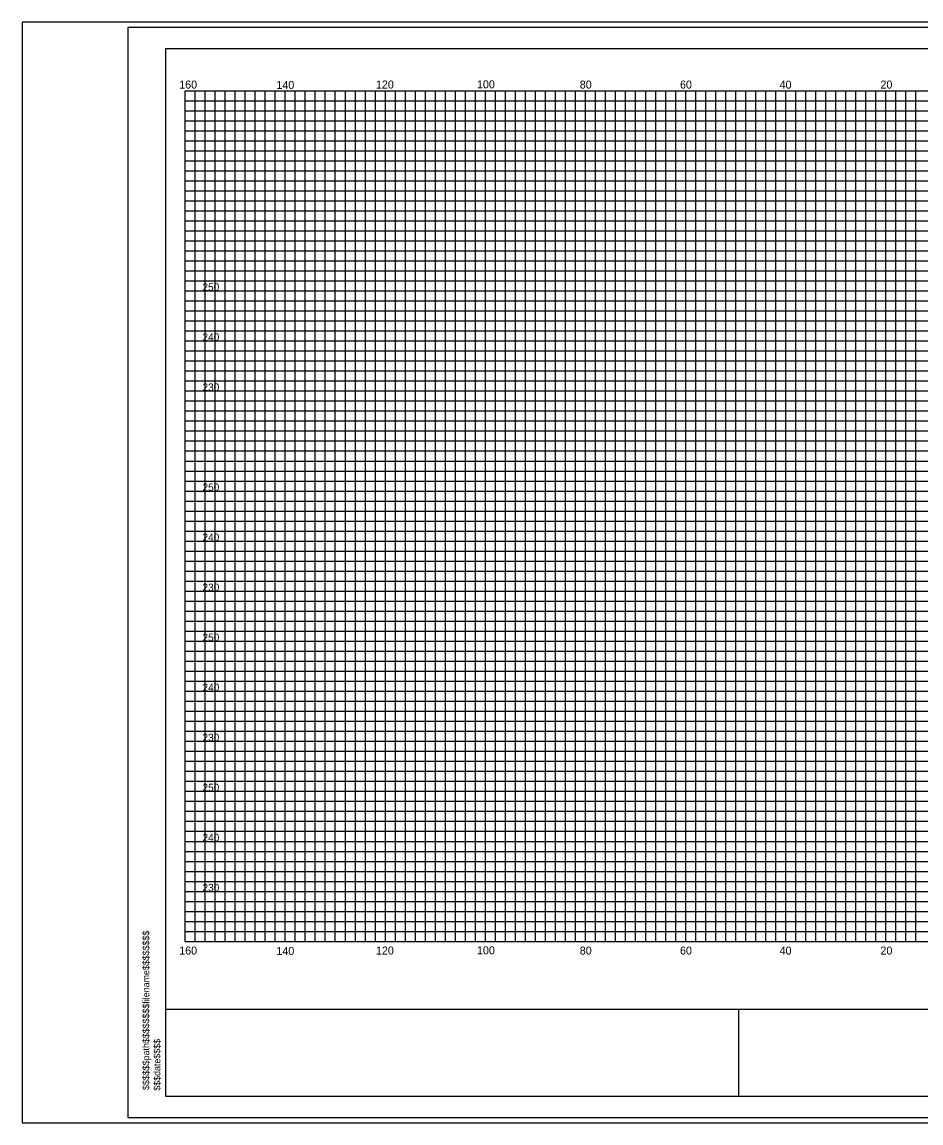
# Model space of a CAD drawing. Extents: x 967 to 1326, y 964 to 1744.
# Drawn here: x 967.4 to 1147, y 963.7 to 1183.7 of the extents above; entities that cross this region are included whole.
import ezdxf

# ---------------------------------------------------------------- set-up
doc = ezdxf.new("R2010")
doc.units = 0
for name, color, linetype in [('Default', 7, 'Continuous'), ('RD_PD_PaveShd', 7, 'Continuous'), ('RD_XS_CurbBase', 7, 'Continuous'), ('RD_XS_TX_Elev_PR', 7, 'Continuous'), ('RD_XS_TX_MkPT', 7, 'Continuous'), ('RD_XS_TX_Slope', 7, 'Continuous'), ('RD_XS_TX_TOC', 7, 'Continuous')]:
    doc.layers.add(name, color=color, linetype=linetype)

msp = doc.modelspace()

# ---------------------------------------------------------------- linework, layer by layer
at = {"layer": 'RD_PD_PaveShd'}
for p, q in [((996.11, 968.98), (996.11, 1178.46)), ((996.11, 1178.46), (1323.89, 1178.46)), ((996.11, 986.49), (1323.89, 986.49)), ((1110.59, 968.98), (1110.59, 986.56)), ((1323.89, 968.98), (996.11, 968.98))]:
    msp.add_line(p, q, dxfattribs=at)
at = {"layer": 'RD_XS_CurbBase'}
msp.add_lwpolyline([(967.41, 963.72), (1326.28, 963.72), (1326.28, 1183.72), (967.41, 1183.72)], close=True, dxfattribs=at)
at = {"layer": 'RD_XS_TX_Elev_PR'}
for p, q in [((1000, 1170), (1320, 1170)), ((1000, 1000), (1000, 1170)), ((1010, 1000), (1010, 1170)), ((1020, 1000), (1020, 1170)), ((1030, 1000), (1030, 1170)), ((1040, 1000), (1040, 1170)), ((1050, 1000), (1050, 1170)), ((1060, 1000), (1060, 1170)), ((1070, 1000), (1070, 1170)), ((1080, 1000), (1080, 1170)), ((1090, 1000), (1090, 1170)), ((1100, 1000), (1100, 1170)), ((1110, 1000), (1110, 1170)), ((1120, 1000), (1120, 1170)), ((1130, 1000), (1130, 1170)), ((1140, 1000), (1140, 1170)), ((1000, 1160), (1320, 1160)), ((1000, 1150), (1320, 1150)), ((1000, 1140), (1320, 1140)), ((1000, 1130), (1320, 1130)), ((1000, 1120), (1320, 1120)), ((1000, 1110), (1320, 1110)), ((1000, 1100), (1320, 1100)), ((1000, 1090), (1320, 1090)), ((1000, 1080), (1320, 1080)), ((1000, 1070), (1320, 1070)), ((1000, 1060), (1320, 1060)), ((1000, 1050), (1320, 1050)), ((1000, 1040), (1320, 1040)), ((1000, 1030), (1320, 1030)), ((1000, 1020), (1320, 1020)), ((1000, 1010), (1320, 1010)), ((1000, 1000), (1320, 1000))]:
    msp.add_line(p, q, dxfattribs=at)
at = {"layer": 'RD_XS_TX_Slope'}
for p, q in [((1002, 1000), (1002, 1170)), ((1004, 1000), (1004, 1170)), ((1006, 1000), (1006, 1170)), ((1008, 1000), (1008, 1170)), ((1012, 1000), (1012, 1170)), ((1014, 1000), (1014, 1170)), ((1016, 1000), (1016, 1170)), ((1018, 1000), (1018, 1170)), ((1022, 1000), (1022, 1170)), ((1024, 1000), (1024, 1170)), ((1026, 1000), (1026, 1170)), ((1028, 1000), (1028, 1170)), ((1032, 1000), (1032, 1170)), ((1034, 1000), (1034, 1170)), ((1036, 1000), (1036, 1170)), ((1038, 1000), (1038, 1170)), ((1042, 1000), (1042, 1170)), ((1044, 1000), (1044, 1170)), ((1046, 1000), (1046, 1170)), ((1048, 1000), (1048, 1170)), ((1052, 1000), (1052, 1170)), ((1054, 1000), (1054, 1170)), ((1056, 1000), (1056, 1170)), ((1058, 1000), (1058, 1170)), ((1062, 1000), (1062, 1170)), ((1064, 1000), (1064, 1170)), ((1066, 1000), (1066, 1170)), ((1068, 1000), (1068, 1170)), ((1072, 1000), (1072, 1170)), ((1074, 1000), (1074, 1170)), ((1076, 1000), (1076, 1170)), ((1078, 1000), (1078, 1170)), ((1082, 1000), (1082, 1170)), ((1084, 1000), (1084, 1170)), ((1086, 1000), (1086, 1170)), ((1088, 1000), (1088, 1170)), ((1092, 1000), (1092, 1170)), ((1094, 1000), (1094, 1170)), ((1096, 1000), (1096, 1170)), ((1098, 1000), (1098, 1170)), ((1102, 1000), (1102, 1170)), ((1104, 1000), (1104, 1170)), ((1106, 1000), (1106, 1170)), ((1108, 1000), (1108, 1170)), ((1112, 1000), (1112, 1170)), ((1114, 1000), (1114, 1170)), ((1116, 1000), (1116, 1170)), ((1118, 1000), (1118, 1170)), ((1122, 1000), (1122, 1170)), ((1124, 1000), (1124, 1170)), ((1126, 1000), (1126, 1170)), ((1128, 1000), (1128, 1170)), ((1132, 1000), (1132, 1170)), ((1134, 1000), (1134, 1170)), ((1136, 1000), (1136, 1170)), ((1138, 1000), (1138, 1170)), ((1142, 1000), (1142, 1170)), ((1144, 1000), (1144, 1170)), ((1146, 1000), (1146, 1170)), ((1000, 1168), (1320, 1168)), ((1000, 1166), (1320, 1166)), ((1000, 1164), (1320, 1164)), ((1000, 1162), (1320, 1162)), ((1000, 1158), (1320, 1158)), ((1000, 1156), (1320, 1156)), ((1000, 1154), (1320, 1154)), ((1000, 1152), (1320, 1152)), ((1000, 1148), (1320, 1148)), ((1000, 1146), (1320, 1146)), ((1000, 1144), (1320, 1144)), ((1000, 1142), (1320, 1142)), ((1000, 1138), (1320, 1138)), ((1000, 1136), (1320, 1136)), ((1000, 1134), (1320, 1134)), ((1000, 1132), (1320, 1132)), ((1000, 1128), (1320, 1128)), ((1000, 1126), (1320, 1126)), ((1000, 1124), (1320, 1124)), ((1000, 1122), (1320, 1122)), ((1000, 1118), (1320, 1118)), ((1000, 1116), (1320, 1116)), ((1000, 1114), (1320, 1114)), ((1000, 1112), (1320, 1112)), ((1000, 1108), (1320, 1108)), ((1000, 1106), (1320, 1106)), ((1000, 1104), (1320, 1104)), ((1000, 1102), (1320, 1102)), ((1000, 1098), (1320, 1098)), ((1000, 1096), (1320, 1096)), ((1000, 1094), (1320, 1094)), ((1000, 1092), (1320, 1092)), ((1000, 1088), (1320, 1088)), ((1000, 1086), (1320, 1086)), ((1000, 1084), (1320, 1084)), ((1000, 1082), (1320, 1082)), ((1000, 1078), (1320, 1078)), ((1000, 1076), (1320, 1076)), ((1000, 1074), (1320, 1074)), ((1000, 1072), (1320, 1072)), ((1000, 1068), (1320, 1068)), ((1000, 1066), (1320, 1066)), ((1000, 1064), (1320, 1064)), ((1000, 1062), (1320, 1062)), ((1000, 1058), (1320, 1058)), ((1000, 1056), (1320, 1056)), ((1000, 1054), (1320, 1054)), ((1000, 1052), (1320, 1052)), ((1000, 1048), (1320, 1048)), ((1000, 1046), (1320, 1046)), ((1000, 1044), (1320, 1044)), ((1000, 1042), (1320, 1042)), ((1000, 1038), (1320, 1038)), ((1000, 1036), (1320, 1036)), ((1000, 1034), (1320, 1034)), ((1000, 1032), (1320, 1032)), ((1000, 1028), (1320, 1028)), ((1000, 1026), (1320, 1026)), ((1000, 1024), (1320, 1024)), ((1000, 1022), (1320, 1022)), ((1000, 1018), (1320, 1018)), ((1000, 1016), (1320, 1016)), ((1000, 1014), (1320, 1014)), ((1000, 1012), (1320, 1012)), ((1000, 1008), (1320, 1008)), ((1000, 1006), (1320, 1006)), ((1000, 1004), (1320, 1004)), ((1000, 1002), (1320, 1002))]:
    msp.add_line(p, q, dxfattribs=at)
at = {"layer": 'RD_XS_TX_TOC'}
for points in [[(967.41, 963.72), (1326.28, 963.72), (1326.28, 1183.72), (967.41, 1183.72)], [(988.52, 964.84), (1326.28, 964.84), (1326.28, 1182.6), (988.52, 1182.6)]]:
    msp.add_lwpolyline(points, close=True, dxfattribs=at)

# ---------------------------------------------------------------- texts
at = {"layer": 'Default'}
for s, p in [('250', (1003.47, 1130)), ('240', (1003.47, 1120)), ('230', (1003.47, 1110)), ('250', (1003.47, 1090)), ('240', (1003.47, 1080)), ('230', (1003.47, 1070)), ('250', (1003.47, 1060)), ('240', (1003.47, 1050)), ('230', (1003.47, 1040)), ('250', (1003.47, 1030)), ('240', (1003.47, 1020)), ('230', (1003.47, 1010))]:
    msp.add_text(s, height=1.5, dxfattribs=at).set_placement(p)
for s, p in [('$$$$$$path$$$$$$$$filename$$$$$$$$', (992.83, 970.31)), ('$$$date$$$$', (995.04, 970.17))]:
    msp.add_text(s, height=1.3258, rotation=90, dxfattribs=at).set_placement(p)
at = {"layer": 'RD_XS_TX_MkPT'}
for s, p in [('160', (998.81, 1170.42)), ('140', (1018.23, 1170.34)), ('120', (1038.12, 1170.43)), ('100', (1058.3, 1170.47)), ('80', (1078.84, 1170.42)), ('60', (1098.86, 1170.42)), ('40', (1118.75, 1170.41)), ('20', (1138.91, 1170.42)), ('160', (998.81, 997.37)), ('140', (1018.23, 997.29)), ('120', (1038.12, 997.38)), ('100', (1058.3, 997.42)), ('80', (1078.84, 997.37)), ('60', (1098.86, 997.37)), ('40', (1118.75, 997.36)), ('20', (1138.91, 997.37))]:
    msp.add_text(s, height=1.6, dxfattribs=at).set_placement(p)

doc.saveas('drawing.dxf')
